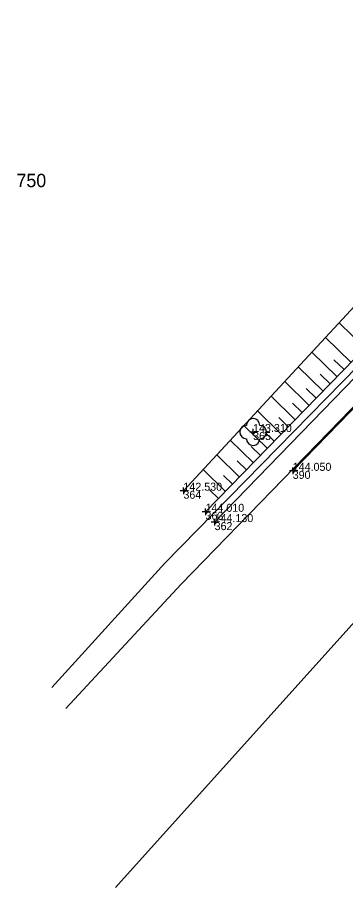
# Model space of a CAD drawing. Extents: x -748509 to -748117, y -967868 to -967533.
# Drawn here: x -748504.2 to -748479.5, y -967867.8 to -967802.6 of the extents above; entities that cross this region are included whole.
import ezdxf

# ---------------------------------------------------------------- set-up
doc = ezdxf.new("R2010")
doc.units = 0
for name, color, linetype in [('Body polohopisu', 7, 'Continuous'), ('KM', 7, 'Continuous'), ('Rozhraní ploch', 7, 'Continuous'), ('Stromy_porost', 7, 'Continuous'), ('Výškopis', 7, 'Continuous'), ('Výšky bodů', 7, 'Continuous'), ('Čísla bodů', 7, 'Continuous')]:
    doc.layers.add(name, color=color, linetype=linetype)

msp = doc.modelspace()

# ---------------------------------------------------------------- linework, layer by layer
at = {"layer": 'Body polohopisu'}
for p, q in [((-748486.47, -967833.71), (-748486.47, -967833.46)), ((-748486.47, -967833.71), (-748486.72, -967833.71)), ((-748486.47, -967833.71), (-748486.22, -967833.71)), ((-748486.47, -967833.71), (-748486.47, -967833.96)), ((-748483.5, -967836.62), (-748483.75, -967836.62)), ((-748483.5, -967836.62), (-748483.5, -967836.37)), ((-748483.5, -967836.62), (-748483.25, -967836.62)), ((-748483.5, -967836.62), (-748483.5, -967836.87)), ((-748491.7, -967838.11), (-748491.95, -967838.11)), ((-748491.7, -967838.11), (-748491.7, -967837.86)), ((-748491.7, -967838.11), (-748491.45, -967838.11)), ((-748491.7, -967838.11), (-748491.7, -967838.36)), ((-748490.04, -967839.69), (-748490.04, -967839.44)), ((-748490.04, -967839.69), (-748490.29, -967839.69)), ((-748490.04, -967839.69), (-748489.79, -967839.69)), ((-748490.04, -967839.69), (-748490.04, -967839.94)), ((-748489.36, -967840.46), (-748489.61, -967840.46)), ((-748489.36, -967840.46), (-748489.36, -967840.21)), ((-748489.36, -967840.46), (-748489.11, -967840.46)), ((-748489.36, -967840.46), (-748489.36, -967840.71))]:
    msp.add_line(p, q, dxfattribs=at)
at = {"layer": 'KM'}
for points in [[(-748245.234, -967554.317), (-748248, -967560.09), (-748251.25, -967566.35), (-748259.98, -967584.86), (-748268.35, -967600.05), (-748271.49, -967604.68), (-748279.6, -967616.66), (-748283.52, -967622.09), (-748309.26, -967655.94), (-748313.11, -967660.69), (-748315.81, -967663.73), (-748339.38, -967691.21), (-748366.68, -967719.8), (-748398.22, -967751.73), (-748421.72, -967775.27), (-748446.6, -967799.82), (-748468.93, -967821.53), (-748491.86, -967845.1), (-748500.525, -967854.438)], [(-748501.569, -967852.844), (-748493.1, -967843.53), (-748470.1, -967820.11), (-748463.7, -967813.82)], [(-748496.8, -967867.85), (-748462.22, -967829.46), (-748449.56, -967816.94)]]:
    msp.add_lwpolyline(points, dxfattribs=at)
at = {"layer": 'Rozhraní ploch'}
for points in [[(-748339.41, -967690.9), (-748344.15, -967696.07), (-748355.97, -967708.43), (-748366.4, -967719.28), (-748377.52, -967730.86), (-748393.8, -967747.28), (-748406.59, -967760.01), (-748445.94, -967798.94), (-748468.02, -967820.71), (-748483.5, -967836.62)], [(-748489.36, -967840.46), (-748469.8, -967820.34), (-748463.2, -967813.85), (-748463.71, -967813.15)]]:
    msp.add_lwpolyline(points, dxfattribs=at)
at = {"layer": 'Stromy_porost'}
msp.add_circle((-748486.47, -967833.71), 0.0005, dxfattribs=at)
for centre, start, end in [((-748486.47, -967833.21), 0, 179.99999), ((-748486.97, -967833.71), 89.99999, 269.99999), ((-748485.97, -967833.71), 270, 89.99999), ((-748486.47, -967834.21), 179.99999, 359.99999)]:
    msp.add_arc(centre, 0.5, start, end, dxfattribs=at)
at = {"layer": 'Výškopis'}
for points in [[(-748490.04, -967839.69), (-748471.35, -967820.54), (-748463.71, -967813.15), (-748465.99, -967810.06), (-748465.381, -967809.54), (-748464.62, -967808.89), (-748461.19, -967810.67), (-748446.48, -967795.95), (-748440.08, -967788.81), (-748425.07, -967774.06), (-748408.42, -967758.07)], [(-748491.7, -967838.11), (-748473.51, -967818.51), (-748465.99, -967810.06)], [(-748478.07, -967827.425), (-748480.019, -967825.523)], [(-748479.117, -967828.499), (-748481.039, -967826.623)], [(-748480.165, -967829.572), (-748482.06, -967827.723)], [(-748479.641, -967829.035), (-748480.405, -967828.29)], [(-748481.213, -967830.645), (-748483.081, -967828.822)], [(-748480.689, -967830.109), (-748481.441, -967829.374)], [(-748482.26, -967831.719), (-748484.101, -967829.922)], [(-748483.308, -967832.792), (-748485.122, -967831.022)], [(-748481.737, -967831.182), (-748482.478, -967830.458)], [(-748482.784, -967832.256), (-748483.515, -967831.542)], [(-748484.356, -967833.866), (-748486.143, -967832.122)], [(-748483.832, -967833.329), (-748484.552, -967832.626)], [(-748485.403, -967834.939), (-748487.163, -967833.222)], [(-748486.451, -967836.013), (-748488.184, -967834.322)], [(-748484.88, -967834.403), (-748485.589, -967833.71)], [(-748485.927, -967835.476), (-748486.626, -967834.794)], [(-748487.499, -967837.086), (-748489.205, -967835.421)], [(-748486.975, -967836.55), (-748487.663, -967835.878)], [(-748488.547, -967838.16), (-748490.226, -967836.521)], [(-748488.023, -967837.623), (-748488.7, -967836.962)], [(-748489.07, -967838.697), (-748489.737, -967838.046)]]:
    msp.add_lwpolyline(points, dxfattribs=at)

# ---------------------------------------------------------------- texts
at = {"layer": 'KM'}
msp.add_text('750', height=1, dxfattribs=at).set_placement((-748504.226, -967815.362))
at = {"layer": 'Výšky bodů'}
for s, p in [('143.310', (-748486.47, -967833.71)), ('144.050', (-748483.5, -967836.62)), ('142.530', (-748491.7, -967838.11)), ('144.010', (-748490.04, -967839.69)), ('144.130', (-748489.36, -967840.46))]:
    msp.add_text(s, height=0.6, dxfattribs=at).set_placement(p)
at = {"layer": 'Čísla bodů'}
for s, p in [('365', (-748486.47, -967834.31)), ('390', (-748483.5, -967837.22)), ('364', (-748491.7, -967838.71)), ('363', (-748490.04, -967840.29)), ('362', (-748489.36, -967841.06))]:
    msp.add_text(s, height=0.6, dxfattribs=at).set_placement(p)

doc.saveas('drawing.dxf')
